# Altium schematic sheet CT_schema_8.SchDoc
size 146 x 119 mm
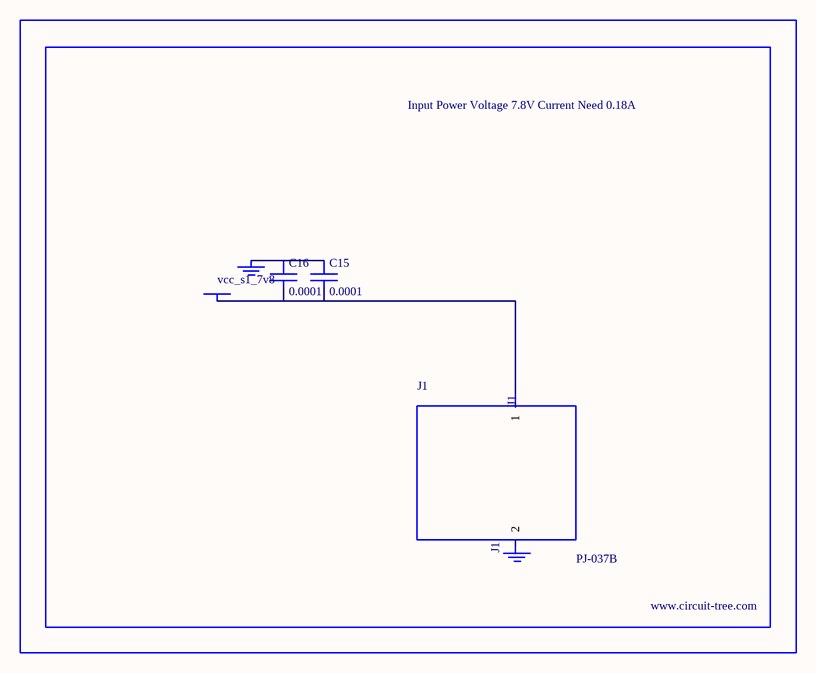
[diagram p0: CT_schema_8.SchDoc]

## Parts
BORDER7  (no value)
C15  0.0001  [EXV-9H]
C16  0.0001  [EXV-9H]
GND_INSTANCE_7_0  (no value)
GND_INSTANCE_7_1  (no value)
J1  PJ-037B  [PJ-037B_PACKAGE]
POWER_INSTANCE_7_0  vcc_s1_7v8

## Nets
NetC15_1: C15.1 C16.1 GND_INSTANCE_7_0.0(GND)
NetC15_2: C15.2 C16.2 J1.1 POWER_INSTANCE_7_0.0(PWR)

Not connected (* = marked no-connect by the designer): GND_INSTANCE_7_1 0(GND); J1 2

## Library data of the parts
BORDER7 = BORDER_PAGE7
C15 C16 = EDK107M035A9HAA
GND_INSTANCE_7_0 GND_INSTANCE_7_1 = GND
POWER_INSTANCE_7_0 = PWR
